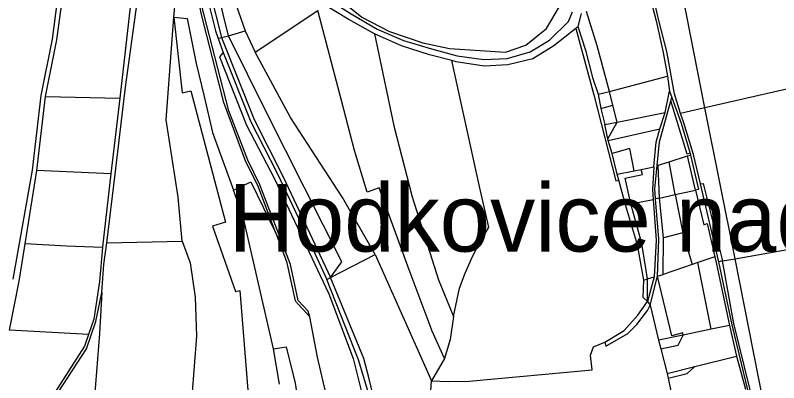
# Model space of a CAD drawing. Extents: x -689422 to -684666, y -987725 to -982160.
# Drawn here: x -687946 to -687268, y -986512 to -986186 of the extents above; entities that cross this region are included whole.
import ezdxf

# ---------------------------------------------------------------- set-up
doc = ezdxf.new("R2010")
doc.units = 0
doc.layers.add('KN_Hranice_katastrální území_popis', color=7, linetype='Continuous')
doc.layers.add('KN_hranice_parcel', color=7, linetype='Continuous')

msp = doc.modelspace()

# ---------------------------------------------------------------- linework, layer by layer
at = {"layer": 'KN_hranice_parcel'}
for p, q in [((-687333.85, -986268.5), (-687356.07, -986154.62)), ((-687843.53, -986176.69), (-687852.93, -986260.13)), ((-687733.06, -986219.3), (-687677.41, -986182.08)), ((-687443.55, -986184.87), (-687446.73, -986196.51)), ((-687446.73, -986196.51), (-687448.38, -986198.32)), ((-687768.29, -986200.34), (-687765.8, -986207.18)), ((-687756.7, -986204.55), (-687741.76, -986200.23)), ((-687741.76, -986200.23), (-687733.06, -986219.3)), ((-687765.8, -986207.18), (-687762.74, -986206.3)), ((-687765.8, -986207.18), (-687761.29, -986219.56)), ((-687762.74, -986206.3), (-687756.7, -986204.55)), ((-687785.22, -986229.28), (-687778.23, -986258.43)), ((-687418.57, -986253.94), (-687367.02, -986240.49)), ((-687367.02, -986240.49), (-687365.13, -986253.92)), ((-687221.4, -986242.72), (-687333.85, -986268.5)), ((-687428.64, -986256.57), (-687418.57, -986253.94)), ((-687428.64, -986256.57), (-687426.21, -986269.28)), ((-687415.44, -986266.22), (-687418.57, -986253.94)), ((-687369.23, -986272.82), (-687365.13, -986253.92)), ((-687365.13, -986253.92), (-687363.12, -986259.43)), ((-687926.73, -986324.1), (-687918.95, -986258.46)), ((-687918.95, -986258.46), (-687852.93, -986260.13)), ((-687852.93, -986260.13), (-687861.01, -986327.01)), ((-687363.94, -986262.32), (-687363.12, -986259.43)), ((-687426.21, -986269.28), (-687415.44, -986266.22)), ((-687426.21, -986269.28), (-687422.72, -986283.33)), ((-687411.64, -986281.15), (-687415.44, -986266.22)), ((-687333.85, -986268.5), (-687355.59, -986273.49)), ((-687307.1, -986402.43), (-687333.85, -986268.5)), ((-687411.64, -986281.15), (-687369.23, -986272.82)), ((-687373.81, -986287.21), (-687369.23, -986272.82)), ((-687422.72, -986283.33), (-687411.64, -986281.15)), ((-687419.95, -986296.13), (-687422.72, -986283.33)), ((-687419.95, -986296.13), (-687411.64, -986281.15)), ((-687419.65, -986297.5), (-687373.81, -986287.21)), ((-687419.65, -986297.5), (-687419.95, -986296.13)), ((-687416.19, -986309), (-687419.65, -986297.5)), ((-687411.55, -986327.53), (-687416.19, -986309)), ((-687365.41, -986316.31), (-687349.27, -986311.27)), ((-687349.27, -986311.27), (-687346.61, -986310.44)), ((-687342.18, -986341.56), (-687349.27, -986311.27)), ((-687347.02, -986309.04), (-687346.61, -986310.44)), ((-687375.34, -986319.4), (-687365.41, -986316.31)), ((-687360.09, -986345.48), (-687365.41, -986316.31)), ((-687937.14, -986389.17), (-687926.73, -986324.1)), ((-687861.01, -986327.01), (-687926.73, -986324.1)), ((-687411.55, -986327.53), (-687396.54, -986324.51)), ((-687396.54, -986324.51), (-687390.37, -986323.27)), ((-687390.37, -986323.27), (-687379.04, -986320.98)), ((-687376.13, -986319.65), (-687375.34, -986319.4)), ((-687374.09, -986348.55), (-687375.34, -986319.4)), ((-687410.17, -986332.67), (-687411.55, -986327.53)), ((-687404.29, -986354.54), (-687410.17, -986332.67)), ((-687321.59, -986405.2), (-687337.65, -986336.11)), ((-687374.09, -986348.55), (-687360.09, -986345.48)), ((-687360.09, -986345.48), (-687342.18, -986341.56)), ((-687360.09, -986345.48), (-687353.55, -986379.41)), ((-687399.7, -986353.64), (-687379.64, -986349.72)), ((-687374.09, -986348.55), (-687377.52, -986349.3)), ((-687370.62, -986383.76), (-687374.09, -986348.55)), ((-687404.29, -986354.54), (-687399.7, -986353.64)), ((-687393.75, -986390.05), (-687404.29, -986354.54)), ((-687389.92, -986389.02), (-687399.7, -986353.64)), ((-687714.68, -986379.59), (-687704.67, -986399.71)), ((-687353.55, -986379.41), (-687370.62, -986383.76)), ((-687353.55, -986379.41), (-687345.06, -986407.56)), ((-687307.1, -986402.43), (-687173.3, -986379)), ((-687370.95, -986416.25), (-687370.62, -986383.76)), ((-687864.46, -986388.44), (-687797.83, -986386.92)), ((-687389.92, -986389.02), (-687393.75, -986390.05)), ((-687388.15, -986421.35), (-687393.75, -986390.05)), ((-687384.68, -986420.27), (-687389.92, -986389.02)), ((-687666.18, -986419.01), (-687626.46, -986398.61)), ((-687626.46, -986398.61), (-687576.47, -986510.61)), ((-687340.04, -986405.87), (-687345.06, -986407.56)), ((-687324.91, -986400.79), (-687340.04, -986405.87)), ((-687328.14, -986464.93), (-687340.04, -986405.87)), ((-687318.33, -986404.4), (-687321.59, -986405.2)), ((-687318.33, -986404.4), (-687307.1, -986402.43)), ((-687280.63, -986535.42), (-687307.1, -986402.43)), ((-687345.06, -986407.56), (-687370.95, -986416.25)), ((-687669.44, -986420.75), (-687666.18, -986419.01)), ((-687388.15, -986421.35), (-687384.68, -986420.27)), ((-687378.8, -986418.44), (-687384.75, -986440.44)), ((-687384.75, -986440.44), (-687384.68, -986420.27)), ((-687384.68, -986420.27), (-687378.8, -986418.44)), ((-687382.47, -986443.64), (-687375.91, -986417.91)), ((-687375.91, -986417.91), (-687370.95, -986416.25)), ((-687384.75, -986440.44), (-687382.47, -986443.64)), ((-687382.47, -986443.64), (-687375.03, -986474.7)), ((-687880.8, -986469.6), (-687950.87, -986465.72)), ((-687328.14, -986464.93), (-687353.17, -986470.15)), ((-687311.95, -986461.55), (-687328.14, -986464.93)), ((-687311.95, -986461.55), (-687305.83, -986488.88)), ((-687880.8, -986469.6), (-687884.49, -986479.98)), ((-687353.17, -986470.15), (-687375.03, -986474.7)), ((-687884.49, -986479.98), (-687916.36, -986529.52)), ((-687375.03, -986474.7), (-687373.04, -986482.3)), ((-687711.3, -986513.54), (-687716.8, -986482.2)), ((-687373.04, -986482.3), (-687367.31, -986504.25)), ((-687565.07, -986490.79), (-687576.47, -986510.61)), ((-687342.73, -986498.11), (-687305.83, -986488.88)), ((-687305.83, -986488.88), (-687297.77, -986518.23)), ((-687367.31, -986504.25), (-687342.73, -986498.11)), ((-687367.31, -986504.25), (-687366.49, -986508.2)), ((-687366.49, -986508.2), (-687361.15, -986534.46)), ((-687578.16, -986535.62), (-687576.47, -986510.61))]:
    msp.add_line(p, q, dxfattribs=at)
for points in [[(-687791.69, -986018), (-687780.07, -986026.97), (-687770.28, -986039.17), (-687758.02, -986059.08), (-687738.67, -986089.16), (-687706.72, -986132.17), (-687686.65, -986153.36), (-687666.84, -986173.32), (-687647.74, -986185.26), (-687624.74, -986198.64), (-687601.36, -986208.73), (-687576.47, -986216.35), (-687553.67, -986222.46), (-687530.03, -986225.82), (-687509.18, -986224.73), (-687488.93, -986219.02), (-687471.61, -986208.6), (-687455.02, -986192.08), (-687451.2, -986183.36)], [(-687864.46, -986388.44), (-687857.26, -986327.29), (-687848.11, -986250.3), (-687837.55, -986175.06), (-687831.58, -986121.26), (-687827.17, -986077.3), (-687823.88, -986050.9), (-687817.51, -986032.37)], [(-687756.7, -986204.55), (-687766.14, -986165.89), (-687762.36, -986150.03), (-687778.25, -986099.91), (-687791.66, -986043.39)], [(-687791.66, -986043.39), (-687774.85, -986096.33), (-687756.01, -986159.48), (-687741.76, -986200.23)], [(-687947.64, -986420.67), (-687930.55, -986323.8), (-687922.96, -986257.64), (-687912.7, -986207.66), (-687903.4, -986134.51), (-687888.89, -986082.81)], [(-687704.67, -986399.71), (-687728.71, -986336.82), (-687739.59, -986314.93), (-687756.39, -986271.2), (-687780.81, -986175.95), (-687792.52, -986091.55)], [(-687805.09, -986188.05), (-687799.7, -986131.22), (-687795.83, -986103.69)], [(-687714.68, -986379.59), (-687730.65, -986337.34), (-687741.14, -986316.36), (-687760.86, -986263.94), (-687780.97, -986184.55), (-687795.83, -986103.69)], [(-687784.66, -986118.51), (-687773.27, -986165.17), (-687762.74, -986206.3)], [(-687784.66, -986118.51), (-687776.6, -986165.78), (-687768.29, -986200.34)], [(-687699.4, -986117.53), (-687697.89, -986132.43), (-687666.24, -986165.31), (-687638.38, -986188.03), (-687613.84, -986200.91), (-687584.24, -986210.99), (-687560.62, -986215.98), (-687510.79, -986219.32), (-687492.62, -986212.95), (-687474.3, -986198.26), (-687462.79, -986178.57), (-687466.57, -986159.93), (-687473.88, -986143.38)], [(-687384.31, -986163.79), (-687377.12, -986191.5), (-687370.9, -986219.45), (-687367.02, -986240.49)], [(-687355.59, -986273.49), (-687360.82, -986256.16), (-687367.68, -986218.73), (-687374.77, -986190.98), (-687380.88, -986163.96)], [(-687918.95, -986258.46), (-687908.92, -986208.25), (-687904.1, -986171.01)], [(-687565.07, -986490.79), (-687576.01, -986466.68), (-687596.22, -986412.38), (-687622.77, -986339.51), (-687633.58, -986343.39), (-687644.92, -986306.42), (-687656.43, -986262), (-687677.41, -986182.08)], [(-687626.95, -986202.99), (-687650.46, -986190), (-687669.81, -986178.19)], [(-687418.57, -986253.94), (-687429.4, -986213.6), (-687438.87, -986183.2)], [(-687797.83, -986386.92), (-687801.17, -986347.9), (-687812.02, -986279.24), (-687805.09, -986188.05)], [(-687805.09, -986188.05), (-687797.65, -986255.17), (-687790, -986253.39), (-687759.36, -986370.08), (-687770.7, -986373.38), (-687750.35, -986431.59), (-687746.52, -986430.63), (-687735.67, -986566.76), (-687730.88, -986571), (-687728.99, -986648.21), (-687717.65, -986667.57)], [(-687805.09, -986188.05), (-687793.42, -986189.36), (-687785.22, -986229.28)], [(-687446.73, -986196.51), (-687439.82, -986217.33), (-687433.59, -986241.63), (-687428.64, -986256.57)], [(-687626.95, -986202.99), (-687609.95, -986284.62), (-687593.74, -986347.38), (-687570.31, -986421.25), (-687556.85, -986453.5)], [(-687558.29, -986226.56), (-687578.27, -986221.62), (-687603.15, -986213.48), (-687626.95, -986202.99)], [(-687448.38, -986198.32), (-687467.81, -986213.61), (-687486.56, -986224.97), (-687508.61, -986230.51), (-687529.86, -986231.66), (-687554.69, -986227.76), (-687558.29, -986226.56)], [(-687448.38, -986198.32), (-687432.27, -986257.14), (-687412.85, -986333.37), (-687410.17, -986332.67)], [(-687762.74, -986206.3), (-687733.81, -986278.9), (-687708.11, -986329.88), (-687666.18, -986419.01)], [(-687666.18, -986419.01), (-687656.04, -986405.13), (-687722.66, -986273.21), (-687756.7, -986204.55)], [(-687761.29, -986219.56), (-687764.64, -986223.28), (-687740.77, -986283.94), (-687715.75, -986331.41), (-687667.6, -986433.6), (-687646.13, -986490.88), (-687635.98, -986531.01)], [(-687761.29, -986219.56), (-687736.81, -986281.12), (-687713.67, -986326.01), (-687693.82, -986367.67), (-687669.44, -986420.75)], [(-687626.46, -986398.61), (-687655.54, -986348.03), (-687701.49, -986277.08), (-687733.06, -986219.3)], [(-687556.85, -986453.5), (-687551.53, -986428.38), (-687546.61, -986415.27), (-687540.21, -986400.4), (-687535.42, -986391.27), (-687525.61, -986374.42), (-687533.83, -986338.21), (-687558.29, -986226.56)], [(-687778.23, -986258.43), (-687770.72, -986290.57), (-687752.26, -986341.57)], [(-687376.13, -986319.65), (-687374.23, -986298.69), (-687363.94, -986262.32)], [(-687347.02, -986309.04), (-687349.62, -986309.77), (-687363.94, -986262.32)], [(-687363.12, -986259.43), (-687354.79, -986282.25), (-687347.02, -986309.04)], [(-687337.65, -986336.11), (-687344.06, -986309.93), (-687352.72, -986280.93), (-687355.59, -986273.49)], [(-687379.04, -986320.98), (-687377.06, -986298.91), (-687373.81, -986287.21)], [(-687396.54, -986324.51), (-687400.56, -986304.67), (-687416.19, -986309)], [(-687346.61, -986310.44), (-687339.53, -986340.98), (-687342.18, -986341.56)], [(-687399.7, -986353.64), (-687404.44, -986331.05), (-687389.13, -986327.72), (-687390.37, -986323.27)], [(-687379.04, -986320.98), (-687380.25, -986340.96), (-687379.64, -986349.72)], [(-687377.52, -986349.3), (-687378.2, -986340.5), (-687376.13, -986319.65)], [(-687861.01, -986327.01), (-687868.13, -986389.21), (-687868.4, -986392.4)], [(-687752.26, -986341.57), (-687736.7, -986334.17), (-687714.68, -986379.59)], [(-687337.65, -986336.11), (-687335.41, -986335.59), (-687318.33, -986404.4)], [(-687716.8, -986482.2), (-687743.28, -986366.37), (-687752.26, -986341.57)], [(-687342.18, -986341.56), (-687334.72, -986372.22), (-687331.73, -986371.28), (-687324.91, -986400.79)], [(-687379.64, -986349.72), (-687377.12, -986385.9), (-687378.8, -986418.44)], [(-687375.91, -986417.91), (-687374.76, -986385.19), (-687377.52, -986349.3)], [(-687714.68, -986379.59), (-687705.16, -986404.79), (-687697.6, -986439.87), (-687684.56, -986454.06)], [(-687950.87, -986465.72), (-687942.42, -986422.17), (-687937.14, -986389.17)], [(-687868.4, -986392.4), (-687900.36, -986391.14), (-687937.14, -986389.17)], [(-687868.4, -986392.4), (-687871, -986422.62), (-687876.01, -986456.13), (-687880.8, -986469.6)], [(-687869.16, -986432.27), (-687867.38, -986407.55), (-687864.46, -986388.44)], [(-687797.83, -986386.92), (-687790.62, -986405.91), (-687786.34, -986436.56), (-687784.88, -986471.18), (-687789.17, -986524.19), (-687787.49, -986570.08)], [(-687684.56, -986454.06), (-687685.97, -986448.79), (-687694.77, -986439.39), (-687701.66, -986407.66), (-687704.67, -986399.71)], [(-687324.91, -986400.79), (-687323.94, -986405.68), (-687311.95, -986461.55)], [(-687291.29, -986536.94), (-687309.62, -986460.91), (-687321.59, -986405.2)], [(-687289.21, -986536.64), (-687308.05, -986459.84), (-687318.33, -986404.4)], [(-687619.88, -986558.31), (-687631.71, -986508.98), (-687636.4, -986490.9), (-687666.18, -986419.01)], [(-687353.17, -986470.15), (-687353.52, -986468.27), (-687363.28, -986470.71), (-687375.91, -986417.91)], [(-687629.94, -986529.26), (-687641.19, -986492.21), (-687669.44, -986420.75)], [(-687384.75, -986440.44), (-687388.64, -986436.91), (-687388.15, -986421.35)], [(-687933.63, -986550.26), (-687915.09, -986532.28), (-687882.71, -986482.32), (-687874.27, -986457.95), (-687869.16, -986432.27)], [(-687869.16, -986432.27), (-687871.04, -986468.74), (-687876.41, -986536.11)], [(-687422.66, -986476.53), (-687405.54, -986466.02), (-687393.26, -986452.49), (-687384.75, -986440.44)], [(-687422.66, -986476.53), (-687421.75, -986480.01), (-687402.36, -986468.84), (-687394.2, -986460.62), (-687384.68, -986448.28), (-687382.47, -986443.64)], [(-687644.64, -986534.13), (-687665.58, -986541.68), (-687677.72, -986489.86), (-687684.56, -986454.06)], [(-687556.85, -986453.5), (-687559.77, -986474.02), (-687565.07, -986490.79)], [(-687373.04, -986482.3), (-687357.61, -986479.15), (-687353.17, -986470.15)], [(-687716.8, -986482.2), (-687705.4, -986480.6), (-687697.4, -986512.8), (-687685.8, -986587.5)], [(-687576.47, -986510.61), (-687561.43, -986511.23), (-687542.94, -986511.02), (-687433.85, -986501.03), (-687435.27, -986488.03), (-687432.69, -986480.62), (-687422.66, -986476.53)], [(-687366.49, -986508.2), (-687349.62, -986504.14), (-687342.73, -986498.11)]]:
    msp.add_lwpolyline(points, dxfattribs=at)

# ---------------------------------------------------------------- texts
at = {"layer": 'KN_Hranice_katastrální území_popis'}
msp.add_text('Hodkovice nad Mohelkou ', height=60, dxfattribs=at).set_placement((-687756.44, -986396.05))

doc.saveas('drawing.dxf')
